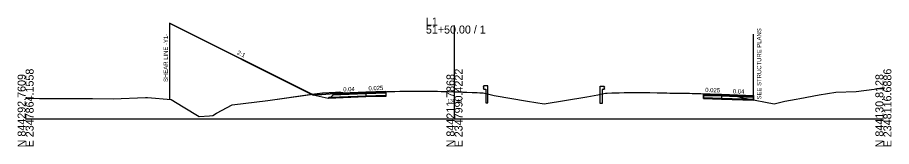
# Model space of a CAD drawing. Extents: x -26 to 2348258, y -10 to 844496.
# Drawn here: x 1298.3 to 1604, y 2490.3 to 2535.3 of the extents above; entities that cross this region are included whole.
import ezdxf

# ---------------------------------------------------------------- set-up
doc = ezdxf.new("R2010")
doc.units = 0
for name, color, linetype in [('Exist Cross Section Cell', 7, 'Continuous'), ('Exist XS Center Line Elevation Label', 7, 'Continuous'), ('Exist XS Ground Line', 7, 'Continuous'), ('Prop CMT Guardrail Graphics', 7, 'Continuous'), ('Prop CMT Pvmt Course 1', 7, 'Continuous'), ('Prop CMT Pvmt Course 2', 7, 'Continuous'), ('Prop CMT Pvmt Course 3', 7, 'Continuous'), ('Prop CMT Pvmt Course 4', 7, 'Continuous'), ('Prop CMT Pvmt Surface', 7, 'Continuous'), ('Prop CMT Shld Paved Course 2', 7, 'Continuous'), ('Prop CMT Shld Paved Course 3', 7, 'Continuous'), ('Prop CMT Shld Paved Course 4', 7, 'Continuous'), ('Prop CMT Slope Grass', 7, 'Continuous'), ('Prop CMT Subgrade Earthwork', 7, 'Continuous'), ('Prop XS Earthwork Shape', 7, 'Continuous'), ('Prop XS SE Text', 7, 'Continuous'), ('Prop XS Shear Point Element', 7, 'Continuous'), ('Prop XS Shear Point Label', 7, 'Continuous')]:
    doc.layers.add(name, color=color, linetype=linetype)

msp = doc.modelspace()

# ---------------------------------------------------------------- linework, layer by layer
at = {"layer": 'Exist Cross Section Cell'}
for p, q in [((1451.19, 2500), (1451.19, 2532.54)), ((1301.19, 2500), (1451.19, 2500)), ((1451.19, 2500), (1601.19, 2500))]:
    msp.add_line(p, q, dxfattribs=at)
at = {"layer": 'Exist XS Ground Line'}
msp.add_lwpolyline([(1301.19, 2507.16), (1306.02, 2507.09), (1308.08, 2507.04), (1311.75, 2507.06), (1319.96, 2507.07), (1324.55, 2507.02), (1331.84, 2506.98), (1343.07, 2507.37), (1343.46, 2507.39), (1343.78, 2507.38), (1352.12, 2506.77), (1356.31, 2504.19), (1361.85, 2500.74), (1365.48, 2501.03), (1366.66, 2501.11), (1367.98, 2501.92), (1373.44, 2504.8), (1385.88, 2506.38), (1405.06, 2509.05), (1409.62, 2509.32), (1410.91, 2509.36), (1412.73, 2509.04), (1414.96, 2509.09), (1415.76, 2509.08), (1416.14, 2509.09), (1417.6, 2509.16), (1418.56, 2509.2), (1419.45, 2509.23), (1420.84, 2509.28), (1421.54, 2509.3), (1422.77, 2509.34), (1424.44, 2509.4), (1424.81, 2509.41), (1425.41, 2509.43), (1426.19, 2509.45), (1427.38, 2509.48), (1430.35, 2509.54), (1432.08, 2509.57), (1433.35, 2509.59), (1434.75, 2509.61), (1435.71, 2509.62), (1436.33, 2509.63), (1439.31, 2509.67), (1439.75, 2509.66), (1440.59, 2509.65), (1442.22, 2509.62), (1443.93, 2509.6), (1445.23, 2509.58), (1446.54, 2509.55), (1448.6, 2509.5), (1450.83, 2509.45), (1451.34, 2509.43), (1453.19, 2509.35), (1453.75, 2509.34), (1454.1, 2509.32), (1455.56, 2509.27), (1457.35, 2509.19), (1457.78, 2509.17), (1459.17, 2509.11), (1460.08, 2509.08), (1460.81, 2509.05), (1461.2, 2509.01), (1462.74, 2508.68), (1465.07, 2508.16), (1476.67, 2506.19), (1482.56, 2505.18), (1497.47, 2507.66), (1501.35, 2508.34), (1502.28, 2508.55), (1504.05, 2508.93), (1504.64, 2508.96), (1506.23, 2509.01), (1507.61, 2509.05), (1508.79, 2509.07), (1510.54, 2509.11), (1511.71, 2509.13), (1513.54, 2509.15), (1514.18, 2509.16), (1514.85, 2509.16), (1516.52, 2509.16), (1517.15, 2509.15), (1518.07, 2509.15), (1519.48, 2509.13), (1522.02, 2509.08), (1522.71, 2509.07), (1524.37, 2509.04), (1525.44, 2509.02), (1526.54, 2508.98), (1527.73, 2508.97), (1528.33, 2508.96), (1529.74, 2508.94), (1531.6, 2508.91), (1531.99, 2508.9), (1533.4, 2508.87), (1534.29, 2508.84), (1536.65, 2508.78), (1537.34, 2508.76), (1538.24, 2508.75), (1540.25, 2508.66), (1540.65, 2508.64), (1541.28, 2508.61), (1543.16, 2508.52), (1544.24, 2508.46), (1546.34, 2508.34), (1548.53, 2508.25), (1548.83, 2508.18), (1549.8, 2507.9), (1551.1, 2507.53), (1552.65, 2507.19), (1553.31, 2507.02), (1563, 2505.15), (1566.74, 2506.12), (1570.69, 2506.79), (1572.02, 2507.06), (1578.69, 2508.33), (1584.57, 2509.3), (1591.63, 2509.53), (1597.93, 2510.38), (1598.88, 2510.55), (1599.34, 2510.61), (1601.19, 2510.85)], dxfattribs=at)
at = {"layer": 'Prop CMT Guardrail Graphics'}
for p, q in [((1461.46, 2511.52), (1461.19, 2511.22)), ((1461.19, 2511.22), (1461.46, 2510.93)), ((1461.46, 2510.93), (1461.19, 2510.64)), ((1461.19, 2510.64), (1461.46, 2510.35)), ((1462.79, 2511.52), (1461.46, 2511.52)), ((1461.46, 2510.35), (1462.13, 2510.35)), ((1462.13, 2510.35), (1462.13, 2505.52)), ((1462.79, 2505.52), (1462.79, 2511.52)), ((1502.12, 2505.35), (1502.12, 2511.35)), ((1502.12, 2511.35), (1503.45, 2511.35)), ((1503.45, 2510.19), (1502.78, 2510.19)), ((1502.78, 2510.19), (1502.78, 2505.35)), ((1503.45, 2511.35), (1503.72, 2511.06)), ((1503.72, 2511.06), (1503.45, 2510.77)), ((1503.45, 2510.77), (1503.72, 2510.48)), ((1503.72, 2510.48), (1503.45, 2510.19)), ((1462.13, 2505.52), (1462.79, 2505.52)), ((1502.78, 2505.35), (1502.12, 2505.35))]:
    msp.add_line(p, q, dxfattribs=at)
at = {"layer": 'Prop CMT Pvmt Course 1'}
for p, q in [((1408.93, 2508.6), (1409.19, 2508.86)), ((1420.19, 2509.17), (1420.19, 2509.3)), ((1420.19, 2509.05), (1420.19, 2509.3)), ((1427.19, 2509.35), (1427.19, 2509.47)), ((1427.19, 2509.22), (1427.19, 2509.47)), ((1538.28, 2508.62), (1538.28, 2508.75)), ((1538.28, 2508.5), (1538.28, 2508.75)), ((1544.59, 2508.47), (1544.59, 2508.59)), ((1544.59, 2508.34), (1544.59, 2508.59))]:
    msp.add_line(p, q, dxfattribs=at)
at = {"layer": 'Prop CMT Pvmt Course 2'}
for p, q in [((1420.19, 2509.05), (1408.93, 2508.6)), ((1427.19, 2509.22), (1420.19, 2509.05)), ((1420.19, 2508.71), (1420.19, 2509.05)), ((1427.19, 2508.89), (1427.19, 2509.22)), ((1538.28, 2508.5), (1544.59, 2508.34)), ((1538.28, 2508.16), (1538.28, 2508.5)), ((1544.59, 2508.34), (1555.72, 2507.9)), ((1544.59, 2508.01), (1544.59, 2508.34))]:
    msp.add_line(p, q, dxfattribs=at)
at = {"layer": 'Prop CMT Pvmt Course 3'}
for p, q in [((1420.19, 2508.72), (1408.58, 2508.25)), ((1427.19, 2508.89), (1420.19, 2508.72)), ((1420.19, 2508.71), (1420.19, 2507.92)), ((1427.19, 2508.89), (1427.19, 2508.1)), ((1538.28, 2508.17), (1544.59, 2508.01)), ((1538.28, 2508.16), (1538.28, 2507.37)), ((1544.59, 2508.01), (1555.72, 2507.56)), ((1544.59, 2508.01), (1544.59, 2507.21))]:
    msp.add_line(p, q, dxfattribs=at)
at = {"layer": 'Prop CMT Pvmt Course 4'}
for p, q in [((1420.19, 2507.59), (1406.95, 2507.1)), ((1420.19, 2507.92), (1407.78, 2507.45)), ((1427.19, 2508.1), (1420.19, 2507.92)), ((1420.19, 2507.59), (1420.19, 2507.92)), ((1427.19, 2507.77), (1420.19, 2507.59)), ((1427.19, 2507.77), (1427.19, 2508.1)), ((1538.28, 2507.37), (1544.59, 2507.22)), ((1538.28, 2507.04), (1538.28, 2507.37)), ((1538.28, 2507.04), (1544.59, 2506.88)), ((1544.59, 2507.22), (1555.72, 2506.79)), ((1544.59, 2506.88), (1544.59, 2507.21)), ((1544.59, 2506.88), (1555.72, 2506.47))]:
    msp.add_line(p, q, dxfattribs=at)
at = {"layer": 'Prop CMT Pvmt Surface'}
for p, q in [((1420.19, 2509.3), (1409.19, 2508.86)), ((1427.19, 2509.47), (1420.19, 2509.3)), ((1538.28, 2508.75), (1544.59, 2508.59)), ((1544.59, 2508.59), (1555.72, 2508.15))]:
    msp.add_line(p, q, dxfattribs=at)
at = {"layer": 'Prop CMT Shld Paved Course 2'}
msp.add_line((1408.93, 2508.6), (1408.59, 2508.26), dxfattribs=at)
at = {"layer": 'Prop CMT Shld Paved Course 3'}
msp.add_line((1407.78, 2507.45), (1408.59, 2508.26), dxfattribs=at)
at = {"layer": 'Prop CMT Shld Paved Course 4'}
for p, q in [((1407.28, 2507.43), (1406.95, 2507.1)), ((1407.78, 2507.45), (1407.28, 2507.43))]:
    msp.add_line(p, q, dxfattribs=at)
at = {"layer": 'Prop CMT Slope Grass'}
for p, q in [((1351.57, 2533.38), (1351.57, 2506.81)), ((1351.57, 2533.38), (1401.8, 2508.27)), ((1409.19, 2508.86), (1401.8, 2508.27)), ((1555.72, 2508.15), (1555.72, 2506.47))]:
    msp.add_line(p, q, dxfattribs=at)
at = {"layer": 'Prop CMT Subgrade Earthwork'}
for p, q in [((1406.95, 2507.1), (1401.8, 2508.27)), ((1420.19, 2507.59), (1406.95, 2507.1)), ((1427.19, 2509.47), (1427.19, 2507.77)), ((1427.19, 2509.47), (1427.19, 2507.77)), ((1538.28, 2508.75), (1538.28, 2507.04)), ((1538.28, 2508.75), (1538.28, 2507.04)), ((1538.28, 2507.04), (1544.59, 2506.88)), ((1544.59, 2506.88), (1555.72, 2506.47))]:
    msp.add_line(p, q, dxfattribs=at)
msp.add_lwpolyline([(1427.19, 2507.77), (1420.19, 2507.59)], dxfattribs=at)
at = {"layer": 'Prop XS Earthwork Shape'}
for points in [[(1351.57, 2506.81), (1352.12, 2506.77), (1356.31, 2504.19), (1361.85, 2500.74), (1365.48, 2501.03), (1366.66, 2501.11), (1367.98, 2501.92), (1373.44, 2504.8), (1385.88, 2506.38), (1401.29, 2508.52), (1351.57, 2533.38)], [(1414.85, 2509.09), (1409.19, 2508.86), (1401.8, 2508.27), (1401.29, 2508.52), (1405.06, 2509.05), (1409.62, 2509.32), (1410.91, 2509.36), (1412.73, 2509.04)], [(1414.85, 2509.09), (1414.96, 2509.09), (1415.76, 2509.08), (1416.14, 2509.09), (1417.6, 2509.16), (1418.56, 2509.2), (1419.45, 2509.23), (1420.84, 2509.28), (1421.54, 2509.3), (1422.77, 2509.34), (1424.44, 2509.4), (1424.81, 2509.41), (1425.41, 2509.43), (1426.19, 2509.45), (1427.19, 2509.47), (1427.19, 2507.77), (1420.19, 2507.59), (1406.95, 2507.1), (1401.8, 2508.27), (1409.19, 2508.86)], [(1538.28, 2508.75), (1540.25, 2508.66), (1540.65, 2508.64), (1541.28, 2508.61), (1543.16, 2508.52), (1544.24, 2508.46), (1546.34, 2508.34), (1548.53, 2508.25), (1548.83, 2508.18), (1549.8, 2507.9), (1551.1, 2507.53), (1552.65, 2507.19), (1553.31, 2507.02), (1555.72, 2506.56), (1555.72, 2506.47), (1544.59, 2506.88), (1538.28, 2507.04)]]:
    msp.add_lwpolyline(points, close=True, dxfattribs=at)
at = {"layer": 'Prop XS Shear Point Element'}
for p, q in [((1351.57, 2533.38), (1351.57, 2506.81)), ((1555.72, 2506.47), (1555.72, 2529.58))]:
    msp.add_line(p, q, dxfattribs=at)

# ---------------------------------------------------------------- texts
at = {"layer": 'Exist Cross Section Cell'}
for s, p in [('L1', (1441.19, 2532.54)), ('51+50.00 / 1', (1441.19, 2529.74))]:
    msp.add_text(s, height=2.8, dxfattribs=at).set_placement(p)
for s, p in [('E 2347864.1558', (1303.99, 2490)), ('E 2347990.4222', (1453.99, 2490)), ('E 2348116.6886', (1603.99, 2490)), ('N 844292.7609', (1301.19, 2490)), ('N 844211.7868', (1451.19, 2490)), ('N 844130.8128', (1601.19, 2490))]:
    msp.add_text(s, height=2.8, rotation=90, dxfattribs=at).set_placement(p)
at = {"layer": 'Exist XS Center Line Elevation Label'}
msp.add_text('138.44', height=1.2, dxfattribs=at).set_placement((1448.74, 2505.64))
at = {"layer": 'Prop XS SE Text'}
for s, rotation, p in [('2:1', 333.4349, (1375.01, 2522.61)), ('0.04', 2.2471, (1412.31, 2509.49)), ('0.025', 1.3886, (1421.12, 2509.9)), ('0.025', 358.5679, (1538.86, 2509.32)), ('0.04', 358.0849, (1548.51, 2508.87))]:
    msp.add_text(s, height=1.5, rotation=rotation, dxfattribs=at).set_placement(p)
at = {"layer": 'Prop XS Shear Point Label'}
for s, p in [('SHEAR LINE -Y1-', (1350.95, 2512.85)), ('SEE STRUCTURE PLANS', (1558.48, 2506.73))]:
    msp.add_text(s, height=1.5, rotation=90, dxfattribs=at).set_placement(p)

doc.saveas('drawing.dxf')
